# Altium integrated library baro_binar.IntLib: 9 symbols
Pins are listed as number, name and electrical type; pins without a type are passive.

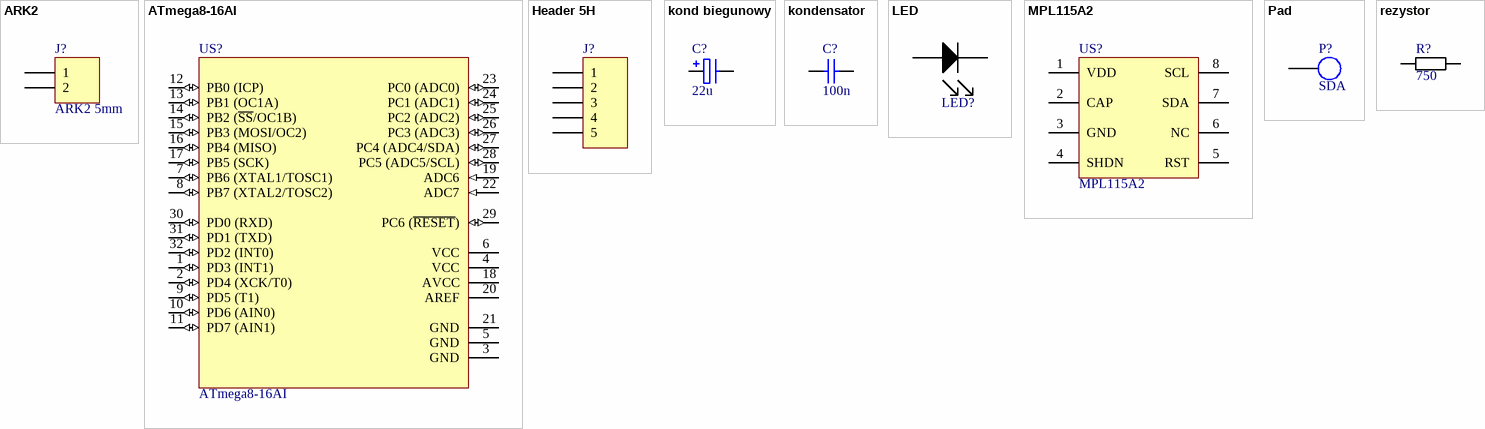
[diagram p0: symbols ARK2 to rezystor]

## ARK2
designator J?, comment ARK2 5mm
footprint ARK2 3,5mm
footprint ARK2 5mm
footprint ARK2 7,5mm
footprint HDR1X2
pins: 1, 2

## ATmega8-16AI
designator US?
8-Bit AVR Microcontroller with 8K Bytes of In-System Programmable Flash Memory
footprint 32A_N (Thin QFP, 32-Leads, Body 7x7mm, Pitch 0.8mm, IPC Medium Density)
footprint 32A_L (Thin QFP, 32-Leads, Body 7x7mm, Pitch 0.8mm, IPC High Density)
footprint 32A_M (Thin QFP, 32-Leads, Body 7x7mm, Pitch 0.8mm, IPC Low Density)
3D model ATMEGA8-32A (32-Pin Thin Quad Flat Pack 0.8 mm Pitch)
pins: 1 PD3 (INT1) (io), 2 PD4 (XCK/T0) (io), 3 GND (power), 4 VCC (power), 5 GND (power), 6 VCC (power), 7 PB6 (XTAL1/TOSC1) (io), 8 PB7 (XTAL2/TOSC2) (io), 9 PD5 (T1) (io), 10 PD6 (AIN0) (io), 11 PD7 (AIN1) (io), 12 PB0 (ICP) (io), 13 PB1 (OC1A) (io), 14 PB2 (~{SS}/OC1B) (io), 15 PB3 (MOSI/OC2) (io), 16 PB4 (MISO) (io), 17 PB5 (SCK) (io), 18 AVCC (power), 19 ADC6 (in), 20 AREF, 21 GND (power), 22 ADC7 (in), 23 PC0 (ADC0) (io), 24 PC1 (ADC1) (io), 25 PC2 (ADC2) (io), 26 PC3 (ADC3) (io), 27 PC4 (ADC4/SDA) (io), 28 PC5 (ADC5/SCL) (io), 29 PC6 (~{RESET}) (io), 30 PD0 (RXD) (io), 31 PD1 (TXD) (io), 32 PD2 (INT0) (io)

## Header 5H
designator J?  (value not drawn)
Header, 5-Pin, Right Angle
footprint HDR1X5H (Connector; Header; 5 Position; Right Angle)
signal-integrity model Connector
pins: 1, 2, 3, 4, 5

## kond biegunowy
designator C?, comment 22u
Polarized Capacitor
footprint Tantal A 3216-1206 (Capacitor, SM Tantalum; Body 3.2 x 1.6 mm (LxW typ))
footprint Tantal B 3528-1411 (Capacitor, SM Tantalum; Body 3.5 x 2.8 mm (LxW typ))
footprint Tantal C 6032-2412 (Capacitor, SM Tantalum; Body 6.0 x 3.2 mm (LxW typ))
footprint Tantal D 7343-2917 (Capacitor, SM Tantalum; Body 7.3 x 4.3 mm (LxW typ))
footprint 2,5/5mm elektrolit
footprint 3,5/7mm elektrolit
footprint 5/10mm elektrolit
footprint KOND_EL 2,5x5
pins: 1, 2
1 alternate drawing of the same symbol

## kondensator
designator C?, comment 100n
footprint kond 2,5mm
footprint kond 5mm
footprint kond 7,5mm
footprint kond 10mm
footprint MELF-0805 (Metal Electrode Face (MELF) Resistor; Body 2 x 1.4 mm (LxDia))
footprint MELF-1206 (Metal Electrode Face (MELF) Resistor; Body 3.2 x 1.8 mm (LxDia))
pins: 1, 2

## LED
designator LED?  (value not drawn)
footprint LED 3mm
footprint LED 5mm
pins: A, K

## MPL115A2
designator US?
footprint MPL115A2
pins: 1 VDD, 2 CAP, 3 GND, 4 SHDN, 5 RST, 6 NC, 7 SDA, 8 SCL

## Pad
designator P?, comment SDA
Pad
footprint pad fi 0,8mm
footprint pad fi 1,5mm
footprint pad fi 1mm
footprint pad fi 2mm
footprint pad fi 2,5mm
footprint pad fi 4mm
footprint Pad SMD 2x4mm
pins: 1

## rezystor
designator R?, comment 750
footprint rez 7,5mm
footprint rez 10mm
footprint rez 12,5mm
footprint rez 15mm
footprint rez 17,5mm
footprint MELF-0805 (Metal Electrode Face (MELF) Resistor; Body 2 x 1.4 mm (LxDia))
footprint MELF-1206 (Metal Electrode Face (MELF) Resistor; Body 3.2 x 1.8 mm (LxDia))
footprint rez_bocznik 20mm
pins: 1, 2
